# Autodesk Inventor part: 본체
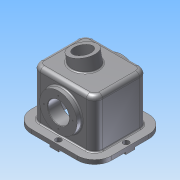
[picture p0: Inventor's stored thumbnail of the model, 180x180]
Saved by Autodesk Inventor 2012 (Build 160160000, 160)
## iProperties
Created: 2008-05
Part Number: 본체
Material: Default
Document SubType Name: Modeling
Designer: net1
Density: 1 g/cm^3
Author: net1
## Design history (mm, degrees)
sketch "스케치1"
  geometry: L1 (0, 0)-(196, 0); L2 (196, 0)-(196, 174); L3 (196, 174)-(0, 174); L4 (0, 174)-(0, 0)
  constraints: 8 end point, 2 parallel, 1 horizontal, 1 perpendicular
  dimensions: "d0" = 196 distance of L2.end L3.end; "d1" = 174 distance of L1.end L2.end
extrude "돌출1" new body sketch "스케치1" distance "d2" = 10; taper "d3" = 0 deg
sketch "스케치2"
  geometry: L1 (196, 174)-(196, 0) reference; L2 (0, 174)-(196, 174) reference; L3 (22, 152)-(174, 152); L4 (174, 152)-(174, 22); L5 (174, 22)-(22, 22); L6 (22, 22)-(22, 152); 4 further points
  constraints: 8 end point, 4 midpoint, 2 parallel, 1 horizontal, 1 horizontal alignment, 1 perpendicular, 1 vertical alignment
  dimensions: "d4" = 152 distance of L3.start L3.end; "d5" = 130 distance of L5.end L3.start
extrude "돌출2" join sketch "스케치2" distance "d6" = 118; taper "d7" = 0 deg
sketch "스케치3"
  geometry: L1 (0, 0)-(-196, 0) reference; L2 (0, 174)-(0, 0) reference; L3 (-196, 174)-(0, 174) reference; L4 (-196, 0)-(-196, 174) reference; L5 (-109, 174)-(-87, 174); L6 (-87, 174)-(-87, 154); L7 (-87, 154)-(-109, 154); L8 (-109, 154)-(-109, 174); L9 (-196, 98)-(-176, 98); L10 (-176, 98)-(-176, 76); L11 (-176, 76)-(-196, 76); L12 (-196, 76)-(-196, 98); L13 (-109, 0)-(-87, 0); L14 (-87, 0)-(-87, 20); L15 (-87, 20)-(-109, 20); L16 (-109, 20)-(-109, 0); L17 (0, 98)-(-20, 98); L18 (-20, 98)-(-20, 76); L19 (-20, 76)-(0, 76); L20 (0, 76)-(0, 98)
  constraints: 32 end point, 8 parallel, 6 equal length, 4 horizontal, 4 perpendicular, 4 point on line, 1 horizontal alignment, 1 vertical alignment
  dimensions: "d10" = 109 distance between parallel lines of L2 L16; "d11" = 98 distance between parallel lines of L3 L11; "d12" = 22 distance of L9.end L10.end; "d13" = 20 distance of L9.start L9.end
extrude "돌출3" join sketch "스케치3" distance "d14" = 5; taper "d15" = 0 deg
fillet "모깎기3" dims "d108" = 10
fillet "모깎기4" dims "d109" = 20
node "작업 평면1"
node "작업 평면2"
node "작업 평면3"
hole "구멍5" diameter "d85" = 9; stored, may be unused: countersink angle "d89" = 90 deg, drill point angle "d91" = 118 deg; dims "d83" = 10, "d84" = 98, "d86" = 9, "d87" = 14, "d88" = 8.6, "d90" = 16
hole "구멍6" diameter "d97" = 9; stored, may be unused: countersink angle "d101" = 90 deg, drill point angle "d103" = 118 deg; dims "d95" = 10, "d96" = 87, "d98" = 9, "d99" = 14, "d100" = 8.6, "d102" = 16
fillet "모깎기2" dims "d107" = 42
node "작업 평면5"
sketch "스케치12"
  geometry: L1 (-45, 133)-(67, 133) reference; L2 (-55, 133)-(-45, 133) reference; L3 (-65, 15)-(-65, 123) reference; L4 (67, 133)-(77, 133) reference; L5 (87, 123)-(87, 15) reference; L6 (0, 5)-(-45, 5) reference; L7 (-45, 5)-(-87, 5) reference; L8 (67, 5)-(22, 5) reference; L9 (109, 5)-(67, 5) reference; L10 (0, 5)-(22, 5) reference; L11 (-55, 5)-(-55, 123); L12 (-55, 123)-(-45, 123); L13 (-45, 123)-(67, 123); L14 (67, 123)-(77, 123); L15 (77, 123)-(77, 5); L16 (109, 15)-(109, 5) reference; L17 (-87, 5)-(-87, 15) reference; A1 r 10 centre (-55, 123) between (-55, 133) and (-65, 123) reference; A2 r 10 centre (77, 123) between (87, 123) and (77, 133) reference
  constraints: 10 end point, 2 parallel, 2 point on line, 12 other
  dimensions: "d110" = 10 distance between parallel lines of L13 L1; "d111" = 20 distance from line of L13.end L5; "d112" = 132 distance from line of L12.end L5; "d113" = 32 distance between parallel lines of L16 L15; "d114" = 32 distance between parallel lines of L17 L11
extrude "돌출8" cut sketch "스케치12" stored distance "d115" = 110; taper "d116" = 0 deg
node "작업 평면6"
sketch "스케치13"
  geometry: L1 (-5, -44)-(-123, -44) reference; L2 (-123, 66)-(-5, 66) reference; L3 (-73, -44)-(-73, 66); L4 (-5, -34)-(-5, -76) reference; L5 (-118.5, -44)-(-108.5, -34); L6 (-108.5, -34)-(-73, -34); L7 (-118.5, 66)-(-108.5, 56); L8 (-108.5, 56)-(-73, 56)
  constraints: 10 end point, 6 point on line, 3 perpendicular, 2 vertical alignment
  dimensions: "d117" = 68 distance between parallel lines of L4 L3; "d118" = 10 distance between parallel lines of L6 L1; "d119" = 10 distance between parallel lines of L2 L8; "d120" = 71 diameter of L7.end L3; "d121" = 91 diameter of L7.start L3
revolve "회전2" sketch "스케치13" stored, may be unused: angle "d122" = 90 deg
sketch "스케치14"
  geometry: L1 (-34.5, 73)-(11, 73); L2 (11, 73)-(-6.88, 157.121); 1 further point
  constraints: 4 end point, 1 horizontal, 1 horizontal alignment, 1 other
  dimensions: "d123" = 78 deg angle of L1 L2; "d124" = 86 distance of L1.end L2.end
node "작업 평면7"
sketch "스케치15"
  geometry: L1 (45, -52.083)-(-45, -52.083) reference; C1 r 31 at (0, 0); 2 further points
  constraints: 1 centre point, 1 midpoint, 1 vertical alignment
  dimensions: "d125" = 62 diameter of C1; "d126" = 52.08304 distance from line of L1 C1.centre
extrude "돌출9" join sketch "스케치15" stored distance "d127" = 110; taper "d128" = 0 deg
hole "구멍7" diameter "d131" = 30; stored, may be unused: countersink angle "d135" = 90 deg, drill point angle "d137" = 118 deg; dims "d129" = 10, "d130" = 10, "d132" = 9, "d133" = 42, "d134" = 25, "d136" = 16
sketch "스케치16"
  geometry: L1 (67, -10)-(112, -10) reference; L2 (45, -15)-(67, -15) reference; C1 r 45.5 at (56, 58); 2 further points
  constraints: 1 centre point, 1 midpoint, 1 vertical alignment
  dimensions: "d138" = 68 distance from line of L1 C1.centre; "d139" = 91 diameter of C1
extrude "돌출10" join sketch "스케치16" distance "d140" = 12; taper "d141" = 0 deg
sketch "스케치17"
  geometry: L1 (67, 15)-(45, 15) reference; L2 (45, 10)-(0, 10) reference; C1 r 45.5 at (56, -58); 2 further points
  constraints: 1 centre point, 1 midpoint, 1 vertical alignment
  dimensions: "d142" = 68 distance from line of L2 C1.centre; "d143" = 91 diameter of C1
extrude "돌출11" join sketch "스케치17" distance "d144" = 12; taper "d145" = 0 deg
hole "구멍8" diameter "d148" = 52; stored, may be unused: countersink angle "d152" = 90 deg, drill point angle "d154" = 118 deg; dims "d146" = 10, "d147" = 10, "d149" = 9, "d150" = 42, "d151" = 25, "d153" = 16
sketch "스케치18" dims "d155" = 70
  geometry: C1 r 26 at (0, 0) reference; C2 r 45.5 at (0, 0) reference; 3 further points
  constraints: 2 vertical alignment, 1 coincident, 2 other
hole "구멍9" sketch "스케치18" at (0, 35) diameter "d156" = 3.242; stored, may be unused: countersink angle "d160" = 90 deg, drill point angle "d162" = 118 deg; dims "d157" = 13, "d158" = 42, "d159" = 25, "d161" = 16
sketch "스케치19"
  geometry: C1 r 1.621 at (0, -35) reference; 1 further point
hole "구멍10" sketch "스케치19" at (0, -35) diameter "d166" = 3.242; stored, may be unused: countersink angle "d170" = 90 deg, drill point angle "d172" = 118 deg; dims "d167" = 13, "d168" = 42, "d169" = 25, "d171" = 16
fillet "모깎기5" dims "d176" = 10
fillet "모깎기6" dims "d177" = 3
fillet "모깎기7" dims "d178" = 3
chamfer "모따기1" distance "d179" = 1; stored, may be unused: second distance "d180" = 2, angle "d181" = 45 deg
fillet "모깎기8" dims "d182" = 0.3
fillet "모깎기9" dims "d183" = 3
sketch "스케치20"
  geometry: L1 (-118, 90)-(-118, 56) reference; L2 (-123, 56)-(-123, 34) reference; 3 further points
  constraints: 1 horizontal alignment, 1 midpoint, 1 other
  dimensions: "d184" = 92 distance from line of L1 point (-26, 45)
feature "엠보싱1" sketch "스케치20" dims "d185" = 1, "d186" = 0
node "솔리드1"
pattern_linear "직사각형 패턴1" dims "d94" = 154
pattern_linear "직사각형 패턴2" dims "d106" = 176
pattern_circular "원형 패턴3" dims angle "d164" = 360 deg
pattern_circular "원형 패턴4" dims angle "d174" = 360 deg
node "투영된 루프1"
